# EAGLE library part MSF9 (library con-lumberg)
MSF CONNECTOR
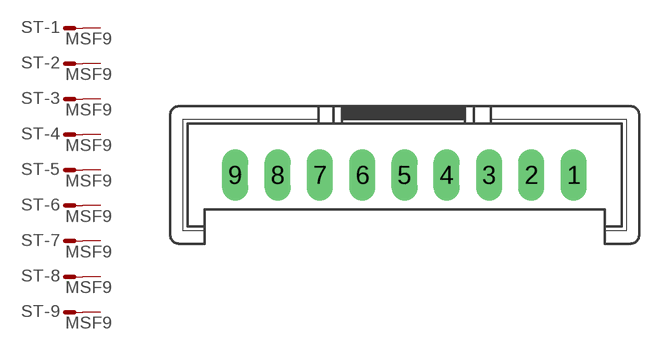
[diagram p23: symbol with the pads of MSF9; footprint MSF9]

Designator prefix ST; gates -1=M -2=M -3=M -4=M -5=M -6=M -7=M -8=M -9=M

## MSF9 (OC_FARNELL: unknown; OC_NEWARK: unknown)  [MSF9]
1  -1:S  pas
2  -2:S  pas
3  -3:S  pas
4  -4:S  pas
5  -5:S  pas
6  -6:S  pas
7  -7:S  pas
8  -8:S  pas
9  -9:S  pas

## Footprint MSF9 (pad centres in mm)
MSF CONNECTOR
drill 1.016 long: 1 10.008,-2.54; 2 7.493,-2.54; 3 5.004,-2.54; 4 2.489,-2.54; 5 0,-2.54; 6 -2.489,-2.54; 7 -5.004,-2.54; 8 -7.493,-2.54; 9 -10.008,-2.54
